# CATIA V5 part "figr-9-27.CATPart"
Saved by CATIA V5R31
Part number: Part1
Bounding box of the stored display mesh (mm): x -75 to 75, y -50 to 50, z 0 to 40
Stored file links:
  D:\PROJECTS\Project 2021\US EDITION\CATIA V5 6R 2021\Resources\Part Files\c09_catia_v5_6r2021_prt\c09_catia_v5_6r2021_prt\figr-9-27.CATPart
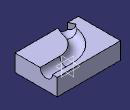
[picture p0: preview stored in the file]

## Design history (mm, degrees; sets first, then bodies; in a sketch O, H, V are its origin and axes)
Body1 (main body)
  Sketch1 on xy-plane, origin (0, 0, 0), H (1, 0, 0), V (0, 1, 0)
    line L1 (-75, 50) -> (75, 50)
    line L2 (75, 50) -> (75, -50)
    line L3 (75, -50) -> (-75, -50)
    line L4 (-75, -50) -> (-75, 50)
    axis line L5 (75, -50) -> (-75, 50)
    length L2 = 100
    length L3 = 150
    horizontal: L1 H, L3 H
    vertical: L2 V, L4 V
    midpoint: O L5
  Pad1: profile Sketch1, direction (0, 0, 1), length 40
  Sketch2 on face of Pad1, origin (75, 0, 0), H (0, 1, 0), V (0, 0, 1)
    arc A1 centre (24.1478, 40) radius 14.6047 from (9.543, 40) to (38.7525, 40) ccw
    point P1 (24.1478, 40)
    reference projected point E1 (24.1478, 40) from vertex of Sketch3
    line L1 (9.543, 40) -> (38.7525, 40)
    coincidence: P1 E1
    horizontal: L1 H
  Sketch3 on face of Pad1, origin (0, 0, 40), H (1, 0, 0), V (0, 1, 0)
    point P1 (75, 24.1478)
    line L1 (75, 24.1478) -> (28.6577, 24.1478)
    arc A1 centre (28.6577, -39.2062) radius 63.354 from (28.6577, 24.1478) to (-33.8383, -28.8149) ccw
    arc A2 centre (-62.192, -24.1005) radius 28.7429 from (-33.8383, -28.8149) to (-49.7271, -50) cw
    point P6 (-49.7271, -50)
    reference projected line E1 (75, -50) -> (75, 50) from edge [face of Pad1 | face of Pad1]
    reference projected line E2 (-75, -50) -> (75, -50) from edge [face of Pad1 | face of Pad1]
    horizontal: L1 H
    tangency: A1 L1, A2 A1
    coincidence: P1 E1, P6 E2
  Slot1: profile Sketch2, centre curve Sketch3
